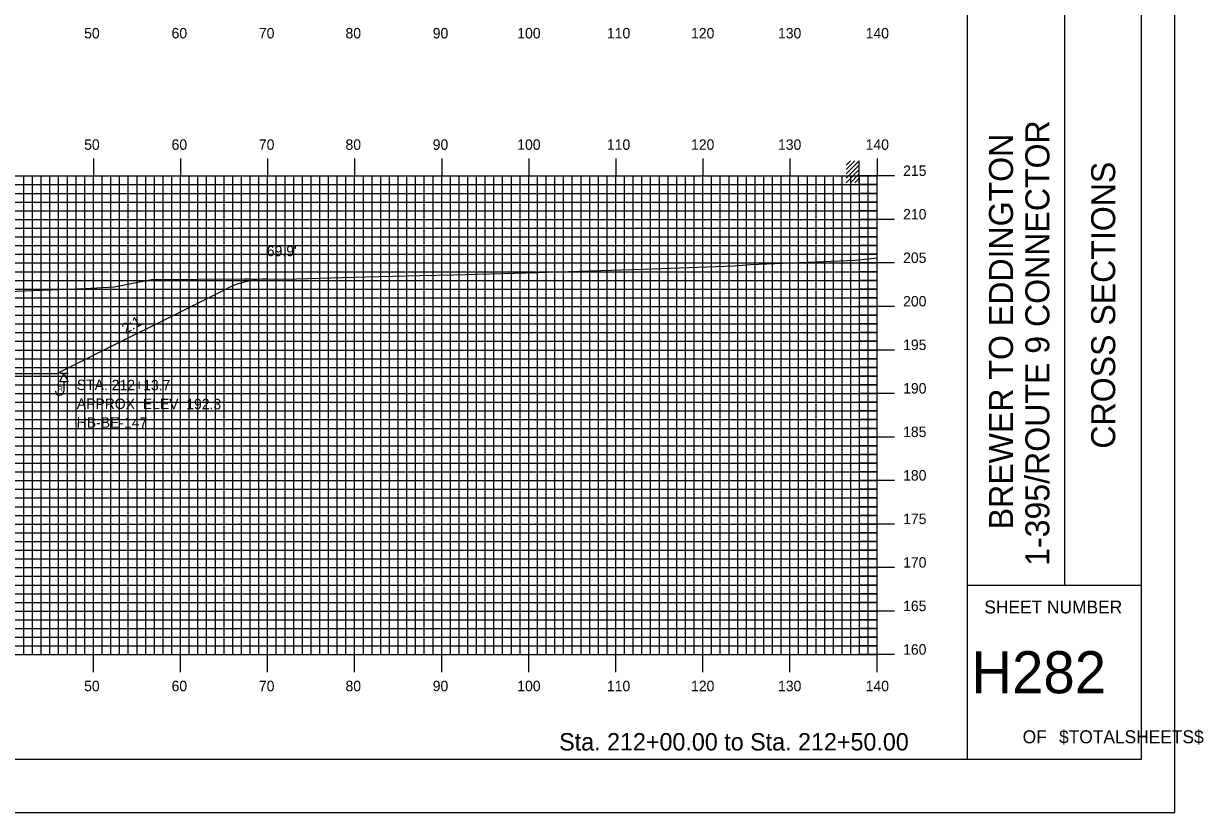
# Model space of a CAD drawing. Extents: x 1795240 to 1795583, y 442591 to 442811.
# Drawn here: x 1795447.3 to 1795582.9, y 442590.5 to 442681.2 of the extents above; entities that cross this region are included whole.
import ezdxf

# ---------------------------------------------------------------- set-up
doc = ezdxf.new("R2010")
doc.units = 0
for name, color, linetype in [('ANNOTATION', 7, 'Continuous'), ('BORDER', 7, 'Continuous'), ('BORING - REFUSAL', 7, 'Continuous'), ('D_Roadway_Centerline', 7, 'Continuous'), ('D_Text_Standard', 7, 'Continuous'), ('H_V ANNOTATION', 7, 'Continuous'), ('M_Buildings_Rooftop', 7, 'Continuous'), ('MAJOR', 7, 'Continuous'), ('MINOR', 7, 'Continuous'), ('PLOT BOUNDARY', 7, 'Continuous'), ('S_Roadway_Centerline', 7, 'Continuous')]:
    doc.layers.add(name, color=color, linetype=linetype)

msp = doc.modelspace()

# ---------------------------------------------------------------- linework, layer by layer
at = {"layer": 'BORDER'}
for p, q in [((1795555.77, 442596.67), (1795555.77, 442806.67)), ((1795566.95, 442616.67), (1795566.95, 442686.67)), ((1795555.77, 442616.67), (1795575.77, 442616.67))]:
    msp.add_line(p, q, dxfattribs=at)
msp.add_lwpolyline([(1795255.77, 442596.67), (1795575.77, 442596.67), (1795575.77, 442806.67), (1795255.77, 442806.67)], close=True, dxfattribs=at)
at = {"layer": 'BORING - REFUSAL'}
for p, q in [((1795452.45, 442640.97), (1795451.49, 442640.97)), ((1795451.97, 442640.01), (1795451.97, 442638.95))]:
    msp.add_line(p, q, dxfattribs=at)
msp.add_lwpolyline([(1795451.97, 442640.97), (1795452.45, 442640.01), (1795451.49, 442640.01)], close=True, dxfattribs=at)
msp.add_arc((1795451.48, 442638.95), 0.485, 180, 0, dxfattribs=at)
at = {"layer": 'D_Roadway_Centerline'}
msp.add_lwpolyline([(1795338.22, 442644.95), (1795361.59, 442633.27), (1795367.59, 442633.27), (1795371.19, 442618.87), (1795375.19, 442619.87), (1795385.37, 442622.41), (1795393.37, 442622.73), (1795405.37, 442622.49), (1795417.37, 442622.25), (1795425.37, 442621.93), (1795435.54, 442619.39), (1795439.54, 442618.39), (1795445.18, 442640.97), (1795451.18, 442640.97), (1795470.79, 442650.77)], dxfattribs=at)
msp.add_arc((1795475.26, 442641.82), 10, 89.883, 116.5651, dxfattribs=at)
at = {"layer": 'M_Buildings_Rooftop'}
for p, q in [((1795541.82, 442663.91), (1795543.33, 442665.42)), ((1795541.82, 442664.4), (1795542.81, 442665.42)), ((1795541.82, 442664.89), (1795542.32, 442665.42)), ((1795543.33, 442662.89), (1795543.33, 442665.42)), ((1795541.82, 442663.42), (1795543.33, 442664.89)), ((1795541.82, 442662.89), (1795543.33, 442664.4)), ((1795542.32, 442662.89), (1795543.33, 442663.91)), ((1795542.81, 442662.89), (1795543.33, 442663.42))]:
    msp.add_line(p, q, dxfattribs=at)
at = {"layer": 'MAJOR'}
for p, q in [((1795455.37, 442665.67), (1795455.37, 442663.67)), ((1795465.37, 442665.67), (1795465.37, 442663.67)), ((1795475.37, 442665.67), (1795475.37, 442663.67)), ((1795485.37, 442665.67), (1795485.37, 442663.67)), ((1795495.37, 442665.67), (1795495.37, 442663.67)), ((1795505.37, 442665.67), (1795505.37, 442663.67)), ((1795515.37, 442665.67), (1795515.37, 442663.67)), ((1795525.37, 442665.67), (1795525.37, 442663.67)), ((1795535.37, 442665.67), (1795535.37, 442663.67)), ((1795545.37, 442665.67), (1795545.37, 442663.67)), ((1795265.37, 442663.67), (1795545.37, 442663.67)), ((1795265.37, 442663.67), (1795545.37, 442663.67)), ((1795455.37, 442608.67), (1795455.37, 442663.67)), ((1795465.37, 442608.67), (1795465.37, 442663.67)), ((1795475.37, 442608.67), (1795475.37, 442663.67)), ((1795485.37, 442608.67), (1795485.37, 442663.67)), ((1795495.37, 442608.67), (1795495.37, 442663.67)), ((1795505.37, 442608.67), (1795505.37, 442663.67)), ((1795515.37, 442608.67), (1795515.37, 442663.67)), ((1795525.37, 442608.67), (1795525.37, 442663.67)), ((1795535.37, 442608.67), (1795535.37, 442663.67)), ((1795547.37, 442663.67), (1795543.36, 442663.67)), ((1795545.37, 442608.67), (1795545.37, 442663.67)), ((1795545.37, 442608.67), (1795545.37, 442663.67)), ((1795265.37, 442658.67), (1795545.37, 442658.67)), ((1795547.37, 442658.67), (1795543.36, 442658.67)), ((1795265.37, 442653.67), (1795545.37, 442653.67)), ((1795547.37, 442653.67), (1795543.36, 442653.67)), ((1795265.37, 442648.67), (1795545.37, 442648.67)), ((1795547.37, 442648.67), (1795543.36, 442648.67)), ((1795265.37, 442643.67), (1795545.37, 442643.67)), ((1795547.37, 442643.67), (1795543.36, 442643.67)), ((1795265.37, 442638.67), (1795545.37, 442638.67)), ((1795547.37, 442638.67), (1795543.36, 442638.67)), ((1795265.37, 442633.67), (1795545.37, 442633.67)), ((1795547.37, 442633.67), (1795543.36, 442633.67)), ((1795265.37, 442628.67), (1795545.37, 442628.67)), ((1795547.37, 442628.67), (1795543.36, 442628.67)), ((1795265.37, 442623.67), (1795545.37, 442623.67)), ((1795547.37, 442623.67), (1795543.36, 442623.67)), ((1795265.37, 442618.67), (1795545.37, 442618.67)), ((1795547.37, 442618.67), (1795543.36, 442618.67)), ((1795265.37, 442613.67), (1795545.37, 442613.67)), ((1795547.37, 442613.67), (1795543.36, 442613.67)), ((1795265.37, 442608.67), (1795545.37, 442608.67)), ((1795265.37, 442608.67), (1795545.37, 442608.67)), ((1795455.37, 442606.66), (1795455.37, 442608.67)), ((1795465.37, 442606.66), (1795465.37, 442608.67)), ((1795475.37, 442606.66), (1795475.37, 442608.67)), ((1795485.37, 442606.66), (1795485.37, 442608.67)), ((1795495.37, 442606.66), (1795495.37, 442608.67)), ((1795505.37, 442606.66), (1795505.37, 442608.67)), ((1795515.37, 442606.66), (1795515.37, 442608.67)), ((1795525.37, 442606.66), (1795525.37, 442608.67)), ((1795535.37, 442606.66), (1795535.37, 442608.67)), ((1795547.37, 442608.67), (1795543.36, 442608.67)), ((1795545.37, 442606.66), (1795545.37, 442608.67))]:
    msp.add_line(p, q, dxfattribs=at)
at = {"layer": 'MINOR'}
for p, q in [((1795265.37, 442662.67), (1795545.37, 442662.67)), ((1795447.37, 442608.67), (1795447.37, 442663.67)), ((1795448.37, 442608.67), (1795448.37, 442663.67)), ((1795449.37, 442608.67), (1795449.37, 442663.67)), ((1795450.37, 442608.67), (1795450.37, 442663.67)), ((1795451.37, 442608.67), (1795451.37, 442663.67)), ((1795452.37, 442608.67), (1795452.37, 442663.67)), ((1795453.37, 442608.67), (1795453.37, 442663.67)), ((1795454.37, 442608.67), (1795454.37, 442663.67)), ((1795456.37, 442608.67), (1795456.37, 442663.67)), ((1795457.37, 442608.67), (1795457.37, 442663.67)), ((1795458.37, 442608.67), (1795458.37, 442663.67)), ((1795459.37, 442608.67), (1795459.37, 442663.67)), ((1795460.37, 442608.67), (1795460.37, 442663.67)), ((1795461.37, 442608.67), (1795461.37, 442663.67)), ((1795462.37, 442608.67), (1795462.37, 442663.67)), ((1795463.37, 442608.67), (1795463.37, 442663.67)), ((1795464.37, 442608.67), (1795464.37, 442663.67)), ((1795466.37, 442608.67), (1795466.37, 442663.67)), ((1795467.37, 442608.67), (1795467.37, 442663.67)), ((1795468.37, 442608.67), (1795468.37, 442663.67)), ((1795469.37, 442608.67), (1795469.37, 442663.67)), ((1795470.37, 442608.67), (1795470.37, 442663.67)), ((1795471.37, 442608.67), (1795471.37, 442663.67)), ((1795472.37, 442608.67), (1795472.37, 442663.67)), ((1795473.37, 442608.67), (1795473.37, 442663.67)), ((1795474.37, 442608.67), (1795474.37, 442663.67)), ((1795476.37, 442608.67), (1795476.37, 442663.67)), ((1795477.37, 442608.67), (1795477.37, 442663.67)), ((1795478.37, 442608.67), (1795478.37, 442663.67)), ((1795479.37, 442608.67), (1795479.37, 442663.67)), ((1795480.37, 442608.67), (1795480.37, 442663.67)), ((1795481.37, 442608.67), (1795481.37, 442663.67)), ((1795482.37, 442608.67), (1795482.37, 442663.67)), ((1795483.37, 442608.67), (1795483.37, 442663.67)), ((1795484.37, 442608.67), (1795484.37, 442663.67)), ((1795486.37, 442608.67), (1795486.37, 442663.67)), ((1795487.37, 442608.67), (1795487.37, 442663.67)), ((1795488.37, 442608.67), (1795488.37, 442663.67)), ((1795489.37, 442608.67), (1795489.37, 442663.67)), ((1795490.37, 442608.67), (1795490.37, 442663.67)), ((1795491.37, 442608.67), (1795491.37, 442663.67)), ((1795492.37, 442608.67), (1795492.37, 442663.67)), ((1795493.37, 442608.67), (1795493.37, 442663.67)), ((1795494.37, 442608.67), (1795494.37, 442663.67)), ((1795496.37, 442608.67), (1795496.37, 442663.67)), ((1795497.37, 442608.67), (1795497.37, 442663.67)), ((1795498.37, 442608.67), (1795498.37, 442663.67)), ((1795499.37, 442608.67), (1795499.37, 442663.67)), ((1795500.37, 442608.67), (1795500.37, 442663.67)), ((1795501.37, 442608.67), (1795501.37, 442663.67)), ((1795502.37, 442608.67), (1795502.37, 442663.67)), ((1795503.37, 442608.67), (1795503.37, 442663.67)), ((1795504.37, 442608.67), (1795504.37, 442663.67)), ((1795506.37, 442608.67), (1795506.37, 442663.67)), ((1795507.37, 442608.67), (1795507.37, 442663.67)), ((1795508.37, 442608.67), (1795508.37, 442663.67)), ((1795509.37, 442608.67), (1795509.37, 442663.67)), ((1795510.37, 442608.67), (1795510.37, 442663.67)), ((1795511.37, 442608.67), (1795511.37, 442663.67)), ((1795512.37, 442608.67), (1795512.37, 442663.67)), ((1795513.37, 442608.67), (1795513.37, 442663.67)), ((1795514.37, 442608.67), (1795514.37, 442663.67)), ((1795516.37, 442608.67), (1795516.37, 442663.67)), ((1795517.37, 442608.67), (1795517.37, 442663.67)), ((1795518.37, 442608.67), (1795518.37, 442663.67)), ((1795519.37, 442608.67), (1795519.37, 442663.67)), ((1795520.37, 442608.67), (1795520.37, 442663.67)), ((1795521.37, 442608.67), (1795521.37, 442663.67)), ((1795522.37, 442608.67), (1795522.37, 442663.67)), ((1795523.37, 442608.67), (1795523.37, 442663.67)), ((1795524.37, 442608.67), (1795524.37, 442663.67)), ((1795526.37, 442608.67), (1795526.37, 442663.67)), ((1795527.37, 442608.67), (1795527.37, 442663.67)), ((1795528.37, 442608.67), (1795528.37, 442663.67)), ((1795529.37, 442608.67), (1795529.37, 442663.67)), ((1795530.37, 442608.67), (1795530.37, 442663.67)), ((1795531.37, 442608.67), (1795531.37, 442663.67)), ((1795532.37, 442608.67), (1795532.37, 442663.67)), ((1795533.37, 442608.67), (1795533.37, 442663.67)), ((1795534.37, 442608.67), (1795534.37, 442663.67)), ((1795536.37, 442608.67), (1795536.37, 442663.67)), ((1795537.37, 442608.67), (1795537.37, 442663.67)), ((1795538.37, 442608.67), (1795538.37, 442663.67)), ((1795539.37, 442608.67), (1795539.37, 442663.67)), ((1795540.37, 442608.67), (1795540.37, 442663.67)), ((1795541.37, 442608.67), (1795541.37, 442663.67)), ((1795542.37, 442608.67), (1795542.37, 442663.67)), ((1795545.37, 442662.67), (1795543.36, 442662.67)), ((1795543.37, 442608.67), (1795543.37, 442663.67)), ((1795544.37, 442608.67), (1795544.37, 442663.67)), ((1795265.37, 442661.67), (1795545.37, 442661.67)), ((1795545.37, 442661.67), (1795543.36, 442661.67)), ((1795265.37, 442660.67), (1795545.37, 442660.67)), ((1795545.37, 442660.67), (1795543.36, 442660.67)), ((1795265.37, 442659.67), (1795545.37, 442659.67)), ((1795545.37, 442659.67), (1795543.36, 442659.67)), ((1795265.37, 442657.67), (1795545.37, 442657.67)), ((1795545.37, 442657.67), (1795543.36, 442657.67)), ((1795265.37, 442656.67), (1795545.37, 442656.67)), ((1795545.37, 442656.67), (1795543.36, 442656.67)), ((1795265.37, 442655.67), (1795545.37, 442655.67)), ((1795265.37, 442654.67), (1795545.37, 442654.67)), ((1795545.37, 442655.67), (1795543.36, 442655.67)), ((1795545.37, 442654.67), (1795543.36, 442654.67)), ((1795265.37, 442652.67), (1795545.37, 442652.67)), ((1795545.37, 442652.67), (1795543.36, 442652.67)), ((1795265.37, 442651.67), (1795545.37, 442651.67)), ((1795265.37, 442650.67), (1795545.37, 442650.67)), ((1795545.37, 442651.67), (1795543.36, 442651.67)), ((1795545.37, 442650.67), (1795543.36, 442650.67)), ((1795265.37, 442649.67), (1795545.37, 442649.67)), ((1795545.37, 442649.67), (1795543.36, 442649.67)), ((1795265.37, 442647.67), (1795545.37, 442647.67)), ((1795545.37, 442647.67), (1795543.36, 442647.67)), ((1795265.37, 442646.67), (1795545.37, 442646.67)), ((1795545.37, 442646.67), (1795543.36, 442646.67)), ((1795265.37, 442645.67), (1795545.37, 442645.67)), ((1795545.37, 442645.67), (1795543.36, 442645.67)), ((1795265.37, 442644.67), (1795545.37, 442644.67)), ((1795545.37, 442644.67), (1795543.36, 442644.67)), ((1795265.37, 442642.67), (1795545.37, 442642.67)), ((1795545.37, 442642.67), (1795543.36, 442642.67)), ((1795265.37, 442641.67), (1795545.37, 442641.67)), ((1795545.37, 442641.67), (1795543.36, 442641.67)), ((1795265.37, 442640.67), (1795545.37, 442640.67)), ((1795265.37, 442639.67), (1795545.37, 442639.67)), ((1795545.37, 442640.67), (1795543.36, 442640.67)), ((1795545.37, 442639.67), (1795543.36, 442639.67)), ((1795265.37, 442637.67), (1795545.37, 442637.67)), ((1795545.37, 442637.67), (1795543.36, 442637.67)), ((1795265.37, 442636.67), (1795545.37, 442636.67)), ((1795265.37, 442635.67), (1795545.37, 442635.67)), ((1795545.37, 442636.67), (1795543.36, 442636.67)), ((1795545.37, 442635.67), (1795543.36, 442635.67)), ((1795265.37, 442634.67), (1795545.37, 442634.67)), ((1795545.37, 442634.67), (1795543.36, 442634.67)), ((1795265.37, 442632.67), (1795545.37, 442632.67)), ((1795265.37, 442631.67), (1795545.37, 442631.67)), ((1795545.37, 442632.67), (1795543.36, 442632.67)), ((1795545.37, 442631.67), (1795543.36, 442631.67)), ((1795265.37, 442630.67), (1795545.37, 442630.67)), ((1795545.37, 442630.67), (1795543.36, 442630.67)), ((1795265.37, 442629.67), (1795545.37, 442629.67)), ((1795545.37, 442629.67), (1795543.36, 442629.67)), ((1795265.37, 442627.67), (1795545.37, 442627.67)), ((1795545.37, 442627.67), (1795543.36, 442627.67)), ((1795265.37, 442626.67), (1795545.37, 442626.67)), ((1795545.37, 442626.67), (1795543.36, 442626.67)), ((1795265.37, 442625.67), (1795545.37, 442625.67)), ((1795265.37, 442624.67), (1795545.37, 442624.67)), ((1795545.37, 442625.67), (1795543.36, 442625.67)), ((1795545.37, 442624.67), (1795543.36, 442624.67)), ((1795265.37, 442622.67), (1795545.37, 442622.67)), ((1795545.37, 442622.67), (1795543.36, 442622.67)), ((1795265.37, 442621.67), (1795545.37, 442621.67)), ((1795265.37, 442620.67), (1795545.37, 442620.67)), ((1795545.37, 442621.67), (1795543.36, 442621.67)), ((1795545.37, 442620.67), (1795543.36, 442620.67)), ((1795265.37, 442619.67), (1795545.37, 442619.67)), ((1795545.37, 442619.67), (1795543.36, 442619.67)), ((1795265.37, 442617.67), (1795545.37, 442617.67)), ((1795265.37, 442616.67), (1795545.37, 442616.67)), ((1795545.37, 442617.67), (1795543.36, 442617.67)), ((1795545.37, 442616.67), (1795543.36, 442616.67)), ((1795265.37, 442615.67), (1795545.37, 442615.67)), ((1795545.37, 442615.67), (1795543.36, 442615.67)), ((1795265.37, 442614.67), (1795545.37, 442614.67)), ((1795545.37, 442614.67), (1795543.36, 442614.67)), ((1795265.37, 442612.67), (1795545.37, 442612.67)), ((1795545.37, 442612.67), (1795543.36, 442612.67)), ((1795265.37, 442611.67), (1795545.37, 442611.67)), ((1795545.37, 442611.67), (1795543.36, 442611.67)), ((1795265.37, 442610.67), (1795545.37, 442610.67)), ((1795545.37, 442610.67), (1795543.36, 442610.67)), ((1795265.37, 442609.67), (1795545.37, 442609.67)), ((1795545.37, 442609.67), (1795543.36, 442609.67))]:
    msp.add_line(p, q, dxfattribs=at)
at = {"layer": 'PLOT BOUNDARY'}
msp.add_lwpolyline([(1795239.58, 442590.55), (1795579.58, 442590.55), (1795579.58, 442810.55), (1795239.58, 442810.55)], close=True, dxfattribs=at)
at = {"layer": 'S_Roadway_Centerline'}
msp.add_lwpolyline([(1795444.55, 442650.36), (1795454.36, 442650.74), (1795457.77, 442650.94), (1795459.89, 442651.36), (1795462.04, 442651.77), (1795472.67, 442651.84), (1795473.23, 442651.83), (1795477.34, 442651.82), (1795486.61, 442652.07), (1795492.84, 442652.23), (1795496.71, 442652.32), (1795505.03, 442652.52), (1795518.51, 442652.97), (1795528.98, 442653.33), (1795530.86, 442653.48), (1795542.85, 442653.98), (1795545.37, 442654.26)], dxfattribs=at)

# ---------------------------------------------------------------- texts
at = {"layer": 'ANNOTATION'}
msp.add_text('2:1', height=1.2, rotation=29.7449, dxfattribs=at).set_placement((1795459.07, 442645.49))
at = {"layer": 'BORDER'}
for s, p in [('1-395/ROUTE 9 CONNECTOR', (1795565.17, 442618.87)), ('BREWER TO EDDINGTON', (1795560.99, 442623.07)), ('CROSS SECTIONS', (1795572.73, 442632.34))]:
    msp.add_text(s, height=2.7557, rotation=90, dxfattribs=at).set_placement(p)
for s, height, p in [('SHEET NUMBER', 1.4905, (1795557.7, 442613.4)), ('H282', 4.839, (1795556.21, 442604.23)), ('OF', 1.491, (1795562.1, 442598.49)), ('$TOTALSHEETS$', 1.4905, (1795566.28, 442598.49))]:
    msp.add_text(s, height=height, dxfattribs=at).set_placement(p)
at = {"layer": 'BORING - REFUSAL'}
msp.add_text('R', height=0.64, dxfattribs=at).set_placement((1795451.26, 442638.89))
for s, p in [('STA. 212+13.7', (1795453.45, 442639.07)), ('APPROX. ELEV. 192.3', (1795453.45, 442636.91)), ('HB-BE-147', (1795453.44, 442634.75))]:
    msp.add_text(s, height=1.2, rotation=359.8142, dxfattribs=at).set_placement(p)
at = {"layer": 'D_Text_Standard'}
msp.add_text("69.9'", height=1.2, dxfattribs=at).set_placement((1795475.28, 442654.45))
at = {"layer": 'H_V ANNOTATION'}
for s, height, p in [('50', 1.2, (1795454.3, 442679.47)), ('60', 1.2, (1795464.34, 442679.47)), ('70', 1.2, (1795474.37, 442679.47)), ('80', 1.2, (1795484.32, 442679.47)), ('90', 1.2, (1795494.34, 442679.47)), ('100', 1.2, (1795504.05, 442679.47)), ('110', 1.2, (1795514.35, 442679.47)), ('120', 1.2, (1795524.01, 442679.47)), ('130', 1.2, (1795534, 442679.47)), ('140', 1.2, (1795544.07, 442679.47)), ('50', 1.2, (1795454.3, 442666.67)), ('60', 1.2, (1795464.34, 442666.67)), ('70', 1.2, (1795474.37, 442666.67)), ('80', 1.2, (1795484.32, 442666.67)), ('90', 1.2, (1795494.34, 442666.67)), ('100', 1.2, (1795504.05, 442666.67)), ('110', 1.2, (1795514.35, 442666.67)), ('120', 1.2, (1795524.01, 442666.67)), ('130', 1.2, (1795534, 442666.67)), ('140', 1.2, (1795544.07, 442666.67)), ('215', 1.2, (1795548.37, 442663.67)), ('210', 1.2, (1795548.37, 442658.67)), ('205', 1.2, (1795548.37, 442653.67)), ('200', 1.2, (1795548.37, 442648.67)), ('195', 1.2, (1795548.37, 442643.67)), ('190', 1.2, (1795548.37, 442638.67)), ('185', 1.2, (1795548.37, 442633.67)), ('180', 1.2, (1795548.37, 442628.67)), ('175', 1.2, (1795548.37, 442623.67)), ('170', 1.2, (1795548.37, 442618.67)), ('165', 1.2, (1795548.37, 442613.67)), ('160', 1.2, (1795548.37, 442608.67)), ('50', 1.2, (1795454.3, 442604.47)), ('60', 1.2, (1795464.34, 442604.47)), ('70', 1.2, (1795474.37, 442604.47)), ('80', 1.2, (1795484.32, 442604.47)), ('90', 1.2, (1795494.34, 442604.47)), ('100', 1.2, (1795504.05, 442604.47)), ('110', 1.2, (1795514.35, 442604.47)), ('120', 1.2, (1795524.01, 442604.47)), ('130', 1.2, (1795534, 442604.47)), ('140', 1.2, (1795544.07, 442604.47)), ('Sta. 212+00.00 to Sta. 212+50.00', 2.0004, (1795508.86, 442597.66))]:
    msp.add_text(s, height=height, dxfattribs=at).set_placement(p)

doc.saveas('drawing.dxf')
